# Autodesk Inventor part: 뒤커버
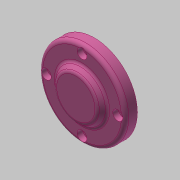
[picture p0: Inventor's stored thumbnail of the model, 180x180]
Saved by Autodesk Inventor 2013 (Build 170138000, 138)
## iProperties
Created: 2017-08
Part Number: 뒤커버
Material: 알루미늄 6061
Document SubType Name: Modeling
Designer: mduedu
Density: 2.71 g/cm^3
Mass: 99.1157 g
Surface Area: 135.95 cm^2
Volume: 36.574 cm^3
Author: mduedu
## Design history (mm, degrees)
sketch "스케치1"
  geometry: C1 r 35 at (0, 0); 1 further point
  constraints: 1 centre point, 1 coincident
  dimensions: "d0" = 70 diameter of C1
extrude "돌출1" new body sketch "스케치1" distance "d1" = 10; taper "d2" = 0 deg
sketch "스케치2"
  geometry: C1 r 21 at (0, 0); 1 further point
  constraints: 1 centre point, 1 coincident
  dimensions: "d3" = 42 diameter of C1
node "작업 평면1"
sketch "스케치3"
  geometry: C1 r 17 at (0, 0); 1 further point
  constraints: 1 centre point, 1 coincident
  dimensions: "d5" = 34 diameter of C1
feature "로프트1" sketch "스케치3" dims "d6" = 0, "d7" = 90 deg, "d8" = 0, "d9" = 90 deg
sketch "스케치4"
  geometry: C1 r 24 at (0, 0); 1 further point
  constraints: 1 centre point, 1 coincident
  dimensions: "d65" = 48 diameter of C1
extrude "돌출2" join sketch "스케치4" distance "d10" = 8; taper "d11" = 0 deg
hole "구멍1" diameter "d14" = 40; stored, may be unused: countersink angle "d18" = 90 deg, drill point angle "d20" = 0 deg; dims "d15" = 6, "d16" = 4, "d17" = 2, "d19" = 12, "d66" = 10, "d67" = 10
hole "구멍2" diameter "d23" = 34; stored, may be unused: countersink angle "d27" = 90 deg, drill point angle "d29" = 0 deg; dims "d24" = 6, "d25" = 4, "d26" = 2, "d28" = 6, "d62" = 10, "d63" = 10
chamfer "모따기1" distance "d39" = 1; stored, may be unused: second distance "d40" = 2, angle "d41" = 45 deg
fillet "모깎기1" dims "d42" = 0.3
fillet "모깎기2" dims "d43" = 3
sketch "스케치5" dims "d44" = 58
  geometry: 6 further points
  constraints: 2 vertical alignment, 1 coincident, 7 other
  dimensions: "d47" = 360 deg dimension on point (0, 0) point (0, 29) (derived)
sketch "스케치6" dims "d64" = 58 (derived)
  geometry: 6 further points
  constraints: 1 coincident, 1 vertical alignment, 6 other
hole "구멍4" sketch "스케치6" at (0, 29), (-29, 0), (29, 0), (0, -29) diameter "d49" = 4.5; stored, may be unused: countersink angle "d53" = 90 deg, drill point angle "d55" = 0 deg; dims "d50" = 6, "d51" = 8, "d52" = 4.6, "d54" = 8
fillet "모깎기3" dims "d56" = 3
fillet "모깎기4" dims "d57" = 3
fillet "모깎기5" dims "d58" = 3
node "솔리드1"
other parameters: "d4" = 5
